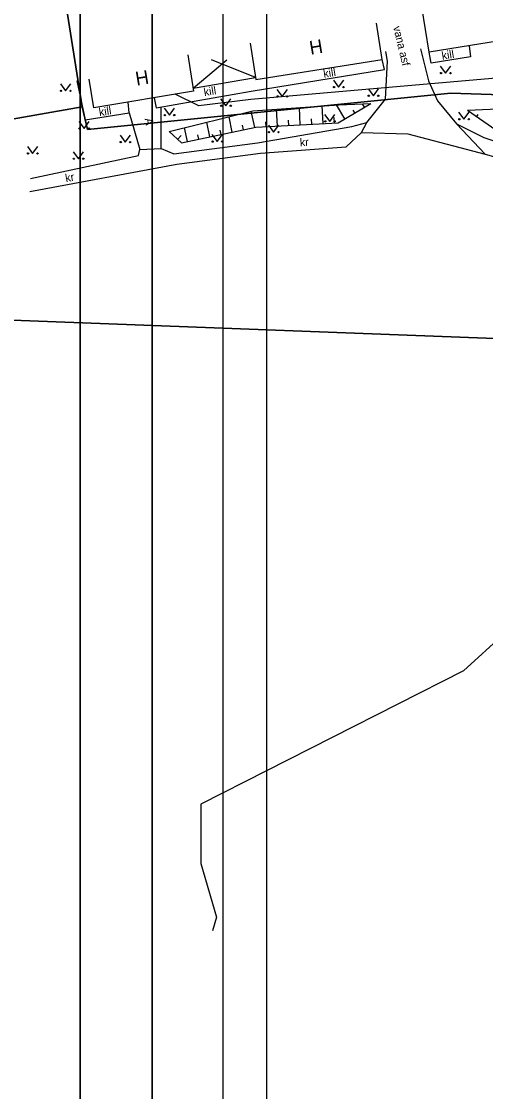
# Model space of a CAD drawing. Extents: x 554947 to 555436, y 6564938 to 6565792.
# Drawn here: x 555187.9 to 555228.5, y 6565518.6 to 6565612.2 of the extents above; entities that cross this region are included whole.
import ezdxf

# ---------------------------------------------------------------- set-up
doc = ezdxf.new("R2010")
doc.units = 0
for name, color, linetype in [('HALJASTUS', 7, 'Continuous'), ('HOONE', 7, 'Continuous'), ('HOONEDET', 7, 'Continuous'), ('PIIR', 7, 'Continuous'), ('PR_SIDE', 7, 'Continuous'), ('RELJEEF', 7, 'Continuous'), ('TEE', 7, 'Continuous'), ('VORMISTUS_2', 7, 'Continuous'), ('VORMISTUS_3', 7, 'Continuous')]:
    doc.layers.add(name, color=color, linetype=linetype)

msp = doc.modelspace()

# ---------------------------------------------------------------- linework, layer by layer
at = {"layer": 'HALJASTUS'}
for p, q in [((555224.56, 6565608.251), (555225.024, 6565607.644)), ((555225.024, 6565607.644), (555225.469, 6565608.251)), ((555191.339, 6565606.7), (555191.803, 6565606.093)), ((555191.803, 6565606.093), (555192.248, 6565606.7)), ((555215.209, 6565607.027), (555215.672, 6565606.42)), ((555215.672, 6565606.42), (555216.118, 6565607.027)), ((555210.276, 6565606.209), (555210.739, 6565605.603)), ((555210.739, 6565605.603), (555211.185, 6565606.209)), ((555218.242, 6565606.269), (555218.705, 6565605.662)), ((555218.705, 6565605.662), (555219.151, 6565606.269)), ((555205.343, 6565605.392), (555205.807, 6565604.785)), ((555205.807, 6565604.785), (555206.252, 6565605.392)), ((555200.41, 6565604.575), (555200.874, 6565603.968)), ((555200.874, 6565603.968), (555201.319, 6565604.575)), ((555214.435, 6565604.027), (555214.899, 6565603.42)), ((555214.899, 6565603.42), (555215.344, 6565604.027)), ((555226.16, 6565604.214), (555226.623, 6565603.607)), ((555226.623, 6565603.607), (555227.069, 6565604.214)), ((555192.953, 6565603.394), (555193.416, 6565602.787)), ((555193.416, 6565602.787), (555193.862, 6565603.394)), ((555209.526, 6565603.079), (555209.989, 6565602.472)), ((555209.989, 6565602.472), (555210.435, 6565603.079)), ((555196.556, 6565602.214), (555197.02, 6565601.607)), ((555197.02, 6565601.607), (555197.465, 6565602.214)), ((555204.594, 6565602.26), (555205.057, 6565601.654)), ((555205.057, 6565601.654), (555205.503, 6565602.26)), ((555188.454, 6565601.223), (555188.917, 6565600.617)), ((555188.917, 6565600.617), (555189.363, 6565601.223)), ((555192.454, 6565600.764), (555192.918, 6565600.157)), ((555192.918, 6565600.157), (555193.363, 6565600.764))]:
    msp.add_line(p, q, dxfattribs=at)
for centre in [(555224.623, 6565607.644), (555225.451, 6565607.644), (555191.402, 6565606.093), (555192.23, 6565606.093), (555210.338, 6565605.603), (555211.167, 6565605.603), (555215.271, 6565606.42), (555216.1, 6565606.42), (555218.304, 6565605.662), (555219.133, 6565605.662), (555205.406, 6565604.785), (555206.234, 6565604.785), (555200.473, 6565603.968), (555201.302, 6565603.968), (555193.015, 6565602.787), (555193.844, 6565602.787), (555214.498, 6565603.42), (555215.326, 6565603.42), (555226.222, 6565603.607), (555227.051, 6565603.607), (555209.588, 6565602.472), (555210.417, 6565602.472), (555196.619, 6565601.607), (555197.447, 6565601.607), (555204.656, 6565601.654), (555205.485, 6565601.654), (555188.516, 6565600.617), (555189.345, 6565600.617), (555192.517, 6565600.157), (555193.346, 6565600.157)]:
    msp.add_circle(centre, 0.055, dxfattribs=at)
at = {"layer": 'HOONE'}
for q in [(555205.887, 6565608.788), (555208.41, 6565607.243)]:
    msp.add_line((555202.943, 6565606.321), q, dxfattribs=at)
for points in [[(555227.207, 6565620.08), (555230.727, 6565620.695), (555232.436, 6565610.906), (555223.594, 6565609.458), (555222.944, 6565613.428)], [(555207.931, 6565610.255), (555208.437, 6565607.073), (555219.483, 6565608.833), (555218.977, 6565612.015)], [(555202.477, 6565609.25), (555202.983, 6565606.068), (555194.266, 6565604.597), (555193.862, 6565607.099)]]:
    msp.add_lwpolyline(points, dxfattribs=at)
at = {"layer": 'HOONEDET'}
msp.add_line((555208.41, 6565607.243), (555204.556, 6565608.806), dxfattribs=at)
at = {"layer": 'PIIR'}
for points in [[(555193.24, 6565604.68), (555183.94, 6565663.24), (555223.17, 6565668.21), (555234.35, 6565605.6), (555225.47, 6565605.89), (555193.7, 6565602.7)], [(555121.18, 6565602.26), (555138.98, 6565580.6), (555179.42, 6565586.32), (555242.37, 6565583.94), (555302.6, 6565539.71), (555287.77, 6565518.56), (555207.29, 6565506.14), (555200.64, 6565496.23), (555185.97, 6565502.75), (555177.68, 6565506.44), (555171.49, 6565510.85), (555162.05, 6565514.45), (555140.65, 6565513.25), (555139.49, 6565523.98), (555139.26, 6565529.51), (555141.68, 6565537.52), (555139.64, 6565543.1), (555131.01, 6565550.06), (555126.35, 6565558.74), (555119.63, 6565564.84), (555105.26, 6565587.71), (555099.5, 6565594.91), (555116.17, 6565610.5)]]:
    msp.add_lwpolyline(points, close=True, dxfattribs=at)
for points in [[(555183.94, 6565663.24), (555193.24, 6565604.68), (555160.12, 6565598.86)], [(555144.16, 6565410.6), (555124.27, 6565454.45), (555113.82, 6565475.68), (555076.76, 6565542.38), (555065.78, 6565566.7), (555060.42, 6565583.26), (555057.22, 6565600.73), (555056.61, 6565622.91), (555063.43, 6565647.29), (555114.24, 6565634), (555129.77, 6565611.2), (555130.73, 6565621.32), (555138.66, 6565615.26), (555160.12, 6565598.86), (555193.24, 6565604.68), (555193.7, 6565602.7), (555225.47, 6565605.89), (555234.35, 6565605.6), (555251.24, 6565598.48), (555330.71, 6565538.85), (555343.81, 6565536.56), (555350.68, 6565540.44), (555361.56, 6565549.57), (555393.069, 6565582.099)], [(555393.069, 6565560.972), (555353.12, 6565523.87), (555343.14, 6565512.46), (555302.6, 6565539.71), (555242.37, 6565583.94), (555179.42, 6565586.32), (555138.98, 6565580.6), (555121.18, 6565602.26), (555116.17, 6565610.5), (555109.96, 6565624.83), (555093.56, 6565628.47), (555079.04, 6565618.4), (555074.13, 6565607.82), (555075.34, 6565593.24), (555091.74, 6565551.94), (555171.91, 6565394.64), (555191.35, 6565341.19), (555195.08, 6565294.61), (555195.28, 6565271.63), (555191.64, 6565237.48)]]:
    msp.add_lwpolyline(points, dxfattribs=at)
at = {"layer": 'PR_SIDE'}
for points in [[(555232.137, 6565606.132), (555230.425, 6565607.283), (555207.996, 6565605.334), (555203.457, 6565604.767), (555201.376, 6565605.797)], [(555237.34, 6565587.08), (555237.34, 6565565.16), (555226.585, 6565555.364), (555203.636, 6565543.731), (555203.636, 6565538.53), (555204.984, 6565533.828), (555204.645, 6565532.63)]]:
    msp.add_lwpolyline(points, dxfattribs=at)
at = {"layer": 'RELJEEF'}
for p, q in [((555212.321, 6565603.117), (555212.238, 6565604.632)), ((555214.318, 6565603.225), (555214.234, 6565604.774)), ((555216.22, 6565603.645), (555215.489, 6565604.863)), ((555217.935, 6565604.673), (555217.761, 6565604.964)), ((555206.371, 6565602.474), (555206.088, 6565603.827)), ((555208.329, 6565602.884), (555208.03, 6565604.312)), ((555210.324, 6565603.008), (555210.243, 6565604.491)), ((555215.316, 6565603.28), (555215.291, 6565603.749)), ((555217.077, 6565604.159), (555216.941, 6565604.386)), ((555227.744, 6565603.84), (555227.875, 6565604.027)), ((555202.456, 6565601.654), (555202.204, 6565602.859)), ((555204.414, 6565602.064), (555204.146, 6565603.343)), ((555207.35, 6565602.679), (555207.263, 6565603.096)), ((555209.325, 6565602.953), (555209.301, 6565603.393)), ((555211.322, 6565603.062), (555211.298, 6565603.512)), ((555213.319, 6565603.171), (555213.294, 6565603.631)), ((555201.586, 6565601.845), (555201.892, 6565602.179)), ((555203.435, 6565601.859), (555203.357, 6565602.231)), ((555205.393, 6565602.269), (555205.31, 6565602.664))]:
    msp.add_line(p, q, dxfattribs=at)
for points in [[(555200.848, 6565602.52), (555201.919, 6565601.541), (555208.428, 6565602.904), (555215.64, 6565603.297), (555218.471, 6565604.995)], [(555200.848, 6565602.52), (555208.154, 6565604.342), (555215.674, 6565604.876), (555218.471, 6565604.995)], [(555226.924, 6565604.412), (555230.239, 6565604.548), (555235.266, 6565603.059), (555241.163, 6565600), (555245.981, 6565597.608), (555251.809, 6565593.416), (555260.505, 6565587.172), (555260.967, 6565585.773)], [(555226.924, 6565604.412), (555229.414, 6565602.674), (555235.432, 6565600.97), (555240.514, 6565598.984), (555245.865, 6565595.82), (555251.258, 6565592.646), (555260.036, 6565585.95), (555260.967, 6565585.773)]]:
    msp.add_lwpolyline(points, dxfattribs=at)
at = {"layer": 'TEE'}
for points in [[(555200.15, 6565601.059), (555201.256, 6565600.582), (555208.571, 6565601.538), (555216.818, 6565602.96), (555218.132, 6565603.326), (555219.765, 6565605.375), (555219.956, 6565608.695), (555219.81, 6565609.537)], [(555222.826, 6565609.775), (555223.534, 6565606.972), (555224.328, 6565605.219), (555225.968, 6565603.202), (555228.36, 6565602.005), (555235.567, 6565599.627), (555240.887, 6565596.891)], [(555227.091, 6565610.03), (555227.198, 6565609.049), (555223.754, 6565608.518), (555223.594, 6565609.458)], [(555199.552, 6565605.489), (555199.703, 6565604.603), (555208.021, 6565606.068), (555219.67, 6565607.945), (555219.483, 6565608.833)], [(555192.782, 6565606.963), (555193.499, 6565603.556), (555197.356, 6565604.174), (555197.269, 6565605.104)], [(555197.356, 6565604.174), (555198.283, 6565600.962), (555200.15, 6565601.059), (555200.141, 6565604.68)], [(555217.666, 6565602.458), (555218.132, 6565603.326)], [(555225.968, 6565603.202), (555228.473, 6565600.549)], [(555188.66, 6565597.281), (555201.537, 6565599.665), (555208.847, 6565600.64), (555216.336, 6565601.179), (555217.666, 6565602.458), (555221.722, 6565602.33), (555228.473, 6565600.549), (555235.333, 6565598.633), (555240.887, 6565596.891), (555244.887, 6565594.749), (555249.174, 6565592.129), (555254.043, 6565588.613), (555259.862, 6565584.582), (555262.011, 6565584.54), (555265.231, 6565585.691), (555268.603, 6565589.126), (555270.071, 6565591.77)], [(555188.724, 6565598.434), (555198.176, 6565600.422), (555198.283, 6565600.962)]]:
    msp.add_lwpolyline(points, dxfattribs=at)
at = {"layer": 'VORMISTUS_2'}
for points in [[(554999.363, 6565654.913), (555209.363, 6565654.913), (555209.363, 6565357.913), (554999.363, 6565357.913)], [(555009.363, 6565368.913), (555199.363, 6565368.913), (555199.363, 6565643.913), (555009.363, 6565643.913)], [(555009.363, 6565643.913), (555199.363, 6565643.913), (555199.363, 6565368.913), (555009.363, 6565368.913)]]:
    msp.add_lwpolyline(points, close=True, dxfattribs=at)
at = {"layer": 'VORMISTUS_3'}
for points in [[(555193.069, 6565415.752), (555383.069, 6565415.752), (555383.069, 6565690.752), (555193.069, 6565690.752)], [(555193.069, 6565690.752), (555383.069, 6565690.752), (555383.069, 6565415.752), (555193.069, 6565415.752)], [(555370.569, 6565441.752), (555205.569, 6565441.752), (555205.569, 6565651.752), (555370.569, 6565651.752)]]:
    msp.add_lwpolyline(points, close=True, dxfattribs=at)

# ---------------------------------------------------------------- texts
at = {"layer": 'HOONE'}
for p in [(555213.221, 6565609.24), (555198.011, 6565606.542)]:
    msp.add_text('H', height=1.2, rotation=9.5306, dxfattribs=at).set_placement(p)
at = {"layer": 'TEE'}
for s, rotation, p in [('vana asf', 283.38256, (555220.432, 6565611.663)), ('kill', 9.05624, (555224.733, 6565608.806)), ('kill', 9.05624, (555214.387, 6565607.223)), ('kill', 9.05624, (555203.931, 6565605.626)), ('kill', 9.05624, (555194.767, 6565603.868)), ('A', 279.86105, (555198.715, 6565603.647)), ('kr', 4.06957, (555212.303, 6565601.226)), ('kr', 10.44064, (555191.834, 6565598.104))]:
    msp.add_text(s, height=0.7, rotation=rotation, dxfattribs=at).set_placement(p)

doc.saveas('drawing.dxf')
